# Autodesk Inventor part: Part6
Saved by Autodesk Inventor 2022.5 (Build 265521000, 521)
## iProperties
Created: 2025-01
Part Number: Part6
Material: Generic
Document SubType Name: Modeling
Designer: AdminForWorker
Density: 1 g/cm^3
Appearance: Default
Author: AdminForWorker
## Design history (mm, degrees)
feature "Body2"
body "Solid1"
